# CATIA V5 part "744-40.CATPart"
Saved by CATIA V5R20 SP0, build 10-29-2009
Part number: 744-40
Revision: TUTTO
Definition: NON CONOSCIUTO
Nomenclature: 744-40
Source: Unknown
Bounding box of the stored display mesh (mm): x -33 to 33, y -33.5 to 32.819, z -37 to 45
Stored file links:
  C:\Users\Utente\Desktop\IO LAVORO\3D X SITO CF\X SITO\744\744-40.CATPart
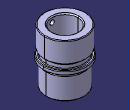
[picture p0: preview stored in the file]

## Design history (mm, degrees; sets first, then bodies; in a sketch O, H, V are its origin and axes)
Body1 "744-40 sol1" (main body)
  Solid1: solid without history
Body2 "IDV1M8_Ingrassatore-1"
  Solid2: solid without history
